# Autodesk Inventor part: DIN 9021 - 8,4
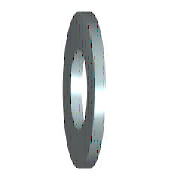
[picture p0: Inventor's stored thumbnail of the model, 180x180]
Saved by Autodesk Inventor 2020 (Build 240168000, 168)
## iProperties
Created: 2008-02
Part Number: DIN 9021 - 8,4
Material: Steel, Mild
Document SubType Name: Modeling
Standard: DIN 9021
Designer: Administrator
Standards Organization: DIN
Language: de-DE
Size Designation: 8,4
Categories: <MemberInstance><Categories><Category DisplayName="Verbindungselemente" InternalName="e4da775c-781d-43d5-af7c-5136215cf5a6" Mnemonic="FSTN"><Category DisplayNam
Mass: 6.24039 g
Surface Area: 9.97518 cm^2
Volume: 0.793943 cm^3
Density: 7.86 g/cm^3
Appearance: Steel
IsCustomPart: 0
Author: Administrator
Revision Number: C
Title: Unterlegscheibe
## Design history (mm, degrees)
workaxis "Work Axis1"
workplane "Work Plane1"
node "Volumenkörper1"
sketch "Skizze"
  geometry: C1 r 12 at (0, 0); C2 r 4.2 at (0, 0); 1 further point
  constraints: 2 centre point, 2 coincident
  dimensions: "d0" = 8.4 diameter of C2 (= SD1); "d1" = 24 diameter of C1 (= SD2)
extrude "Körper" new body sketch "Skizze" distance "d2" = 2 (= SD); taper "d3" = 0 deg
node "Volumenkörpern"
node "Oberflächenkörpern"
other parameters: "SD1" = 8.4 [user parameter; used in 1 equation term], "SD2" = 24 [user parameter; used in 1 equation term], "SD" = 2 [user parameter; used in 1 equation term], "d4" = 0, "d5" = 0, "d6" = 0, "d7" = 0, "NND" = 8 [user parameter]
